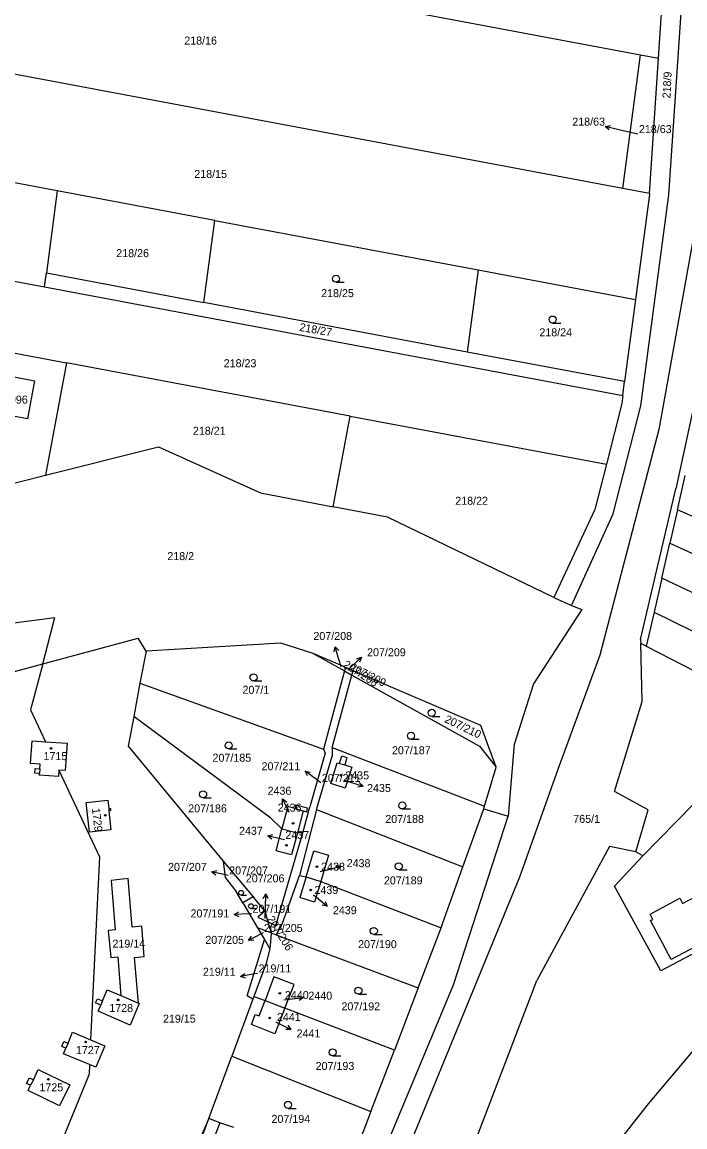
# Model space of a CAD drawing. Extents: x -735249 to -729401, y -1124843 to -1121828.
# Drawn here: x -733671.5 to -733530.7, y -1123483.1 to -1123248.5 of the extents above; entities that cross this region are included whole.
import ezdxf

# ---------------------------------------------------------------- set-up
doc = ezdxf.new("R2010")
doc.units = 0
for name, color, linetype in [('Vrstva 1', 7, 'Continuous'), ('Vrstva 10', 7, 'Continuous'), ('Vrstva 16', 7, 'Continuous'), ('Vrstva 18', 7, 'Continuous'), ('Vrstva 19', 7, 'Continuous'), ('Vrstva 25', 7, 'Continuous'), ('Vrstva 4', 7, 'Continuous')]:
    doc.layers.add(name, color=color, linetype=linetype)

msp = doc.modelspace()

# ---------------------------------------------------------------- linework, layer by layer
at = {"layer": 'Vrstva 1'}
for points in [[(-733736.92, -1123218.48), (-733540.13, -1123255.42)], [(-733536.3, -1123256.14), (-733535.11, -1123238.11)], [(-733534.07, -1123285.18), (-733530.92, -1123238.05)], [(-733543.83, -1123283.81), (-733727.57, -1123249.33)], [(-733543.83, -1123283.81), (-733540.13, -1123255.42)], [(-733540.13, -1123255.42), (-733536.3, -1123256.14)], [(-733538.21, -1123284.87), (-733536.3, -1123256.14)], [(-733664.04, -1123284.33), (-733718.36, -1123274.13)], [(-733664.04, -1123284.33), (-733666.35, -1123301.75)], [(-733630.59, -1123290.61), (-733664.04, -1123284.33)], [(-733538.21, -1123284.87), (-733543.83, -1123283.81)], [(-733538.22, -1123285.05), (-733541.18, -1123307.39)], [(-733540.03, -1123329.93), (-733534.07, -1123285.18)], [(-733538.21, -1123284.87), (-733538.22, -1123285.05)], [(-733632.9, -1123308.03), (-733630.59, -1123290.61)], [(-733630.59, -1123290.61), (-733574.63, -1123301.11)], [(-733520.99, -1123294.03), (-733532.59, -1123347.6)], [(-733710.01, -1123296.6), (-733666.75, -1123304.72)], [(-733666.75, -1123304.72), (-733666.35, -1123301.75)], [(-733666.35, -1123301.75), (-733632.9, -1123308.03)], [(-733574.63, -1123301.11), (-733576.94, -1123318.53)], [(-733574.63, -1123301.11), (-733541.18, -1123307.39)], [(-733666.75, -1123304.72), (-733543.89, -1123327.78)], [(-733576.94, -1123318.53), (-733632.9, -1123308.03)], [(-733541.18, -1123307.39), (-733543.5, -1123324.81)], [(-733702.78, -1123313.18), (-733662.06, -1123320.82)], [(-733543.5, -1123324.81), (-733576.94, -1123318.53)], [(-733662.06, -1123320.82), (-733666.55, -1123344.7)], [(-733601.77, -1123332.14), (-733662.06, -1123320.82)], [(-733674.99, -1123323.44), (-733668.9, -1123324.66), (-733670.38, -1123332.72), (-733676.51, -1123331.56), (-733674.99, -1123323.44)], [(-733543.89, -1123327.78), (-733543.5, -1123324.81)], [(-733544.11, -1123329.44), (-733547.36, -1123342.35)], [(-733545.89, -1123352.88), (-733540.03, -1123329.93)], [(-733543.89, -1123327.78), (-733544.11, -1123329.44)], [(-733605.39, -1123351.42), (-733601.77, -1123332.14)], [(-733601.77, -1123332.14), (-733547.36, -1123342.35)], [(-733666.55, -1123344.7), (-733642.54, -1123338.69)], [(-733642.54, -1123338.69), (-733620.86, -1123348.46)], [(-733547.36, -1123342.35), (-733549.78, -1123351.98)], [(-733687, -1123349.82), (-733666.55, -1123344.7)], [(-733532.26, -1123352.08), (-733530.59, -1123344.79)], [(-733620.86, -1123348.46), (-733605.39, -1123351.42)], [(-733540.08, -1123379.6), (-733532.59, -1123347.6)], [(-733593.86, -1123353.63), (-733605.39, -1123351.42)], [(-733549.78, -1123351.98), (-733558.54, -1123370.66)], [(-733554.78, -1123372.38), (-733545.89, -1123352.88)], [(-733532.26, -1123352.08), (-733533.89, -1123359.16)], [(-733483.93, -1123373.04), (-733532.26, -1123352.08)], [(-733558.54, -1123370.66), (-733593.86, -1123353.63)], [(-733535.59, -1123366.57), (-733533.89, -1123359.16)], [(-733533.89, -1123359.16), (-733485.79, -1123381.01)], [(-733535.59, -1123366.57), (-733537.24, -1123373.77)], [(-733487.7, -1123389.15), (-733535.59, -1123366.57)], [(-733558.54, -1123370.66), (-733554.78, -1123372.38)], [(-733552.6, -1123373.18), (-733562.87, -1123389.01)], [(-733554.78, -1123372.38), (-733552.6, -1123373.18)], [(-733537.24, -1123373.77), (-733538.91, -1123381.02)], [(-733537.24, -1123373.77), (-733489.57, -1123397.16)], [(-733673.24, -1123376.01), (-733664.56, -1123374.88)], [(-733667.14, -1123384.77), (-733664.56, -1123374.88)], [(-733667.14, -1123384.77), (-733646.84, -1123379.28)], [(-733645.17, -1123382.03), (-733646.84, -1123379.28)], [(-733616.54, -1123380.36), (-733645.17, -1123382.03)], [(-733609.7, -1123382.54), (-733616.54, -1123380.36)], [(-733540.08, -1123379.6), (-733540.06, -1123380.46)], [(-733538.91, -1123381.02), (-733540.06, -1123380.46)], [(-733539.76, -1123392.73), (-733540.06, -1123380.46)], [(-733538.91, -1123381.02), (-733491.48, -1123405.34)], [(-733645.17, -1123382.03), (-733646.47, -1123388.87)], [(-733609.7, -1123382.54), (-733603.04, -1123386.25)], [(-733602.84, -1123385.49), (-733609.7, -1123382.54)], [(-733680.02, -1123388.25), (-733667.14, -1123384.77)], [(-733667.14, -1123384.77), (-733669.7, -1123394.55)], [(-733603.04, -1123386.25), (-733607.45, -1123402.89)], [(-733602.84, -1123385.49), (-733603.04, -1123386.25)], [(-733603.04, -1123386.25), (-733601.43, -1123387.15)], [(-733601.17, -1123386.21), (-733602.84, -1123385.49)], [(-733601.43, -1123387.15), (-733601.17, -1123386.21)], [(-733574.03, -1123397.88), (-733601.17, -1123386.21)], [(-733605.65, -1123402.51), (-733601.43, -1123387.15)], [(-733601.43, -1123387.15), (-733574.32, -1123402.24)], [(-733646.47, -1123388.87), (-733647.81, -1123395.96)], [(-733646.47, -1123388.87), (-733607.45, -1123402.89)], [(-733562.87, -1123389.01), (-733566.96, -1123401.86)], [(-733545.62, -1123411.89), (-733539.76, -1123392.73)], [(-733669.7, -1123394.55), (-733666.54, -1123401.28)], [(-733647.81, -1123395.96), (-733649.01, -1123402.27)], [(-733618.66, -1123417.51), (-733647.81, -1123395.96)], [(-733570.75, -1123406.68), (-733574.03, -1123397.88)], [(-733669.72, -1123405.91), (-733669.38, -1123401.08)], [(-733669.38, -1123401.08), (-733666.54, -1123401.28)], [(-733666.54, -1123401.28), (-733661.93, -1123401.61)], [(-733661.93, -1123401.61), (-733662.35, -1123407.43)], [(-733649.01, -1123402.27), (-733628.78, -1123426.64)], [(-733605.65, -1123402.51), (-733605.6, -1123404.35)], [(-733605.65, -1123402.51), (-733573.24, -1123414.96)], [(-733574.32, -1123402.24), (-733570.75, -1123406.68)], [(-733566.96, -1123401.86), (-733568.25, -1123417.12)], [(-733607.12, -1123403.71), (-733610.4, -1123415.14)], [(-733608.94, -1123415.67), (-733605.6, -1123404.35)], [(-733607.45, -1123402.89), (-733607.12, -1123403.71)], [(-733604.08, -1123405.89), (-733603.6, -1123404.31)], [(-733603.6, -1123404.31), (-733602.48, -1123404.65)], [(-733602.48, -1123404.65), (-733602.96, -1123406.23)], [(-733667.69, -1123406.06), (-733669.72, -1123405.91)], [(-733668.81, -1123407.96), (-733668.75, -1123406.97)], [(-733668.75, -1123406.97), (-733667.76, -1123407.04)], [(-733667.76, -1123407.04), (-733667.69, -1123406.06)], [(-733663.68, -1123407.33), (-733663.78, -1123408.71)], [(-733662.35, -1123407.43), (-733663.68, -1123407.33)], [(-733663.68, -1123407.33), (-733655.07, -1123425.73)], [(-733605.9, -1123410.18), (-733604.55, -1123405.77)], [(-733604.55, -1123405.77), (-733604.08, -1123405.89)], [(-733602.96, -1123406.23), (-733601.47, -1123406.68)], [(-733601.47, -1123406.68), (-733602.84, -1123411.13)], [(-733573.24, -1123414.96), (-733570.75, -1123406.68)], [(-733667.83, -1123408.03), (-733668.81, -1123407.96)], [(-733667.86, -1123408.42), (-733667.83, -1123408.03)], [(-733663.78, -1123408.71), (-733667.86, -1123408.42)], [(-733602.84, -1123411.13), (-733605.9, -1123410.18)], [(-733538.5, -1123415.76), (-733545.62, -1123411.89)], [(-733657.87, -1123414.17), (-733653.29, -1123413.69)], [(-733657.21, -1123420.49), (-733657.87, -1123414.17)], [(-733653.29, -1123413.69), (-733653.1, -1123415.49)], [(-733653.1, -1123415.49), (-733652.76, -1123415.46)], [(-733652.72, -1123415.92), (-733653.06, -1123415.95)], [(-733653.06, -1123415.95), (-733652.63, -1123420.01)], [(-733652.76, -1123415.46), (-733652.72, -1123415.92)], [(-733615.06, -1123415.08), (-733616.3, -1123419.76)], [(-733613.57, -1123415.48), (-733615.06, -1123415.08)], [(-733613.37, -1123414.73), (-733613.57, -1123415.48)], [(-733610.84, -1123415.41), (-733613.37, -1123414.73)], [(-733611.77, -1123415.96), (-733613.02, -1123420.64)], [(-733608.94, -1123415.67), (-733612.6, -1123429.68)], [(-733611.87, -1123420.65), (-733610.4, -1123415.14)], [(-733611.77, -1123415.96), (-733611.04, -1123416.16)], [(-733611.04, -1123416.16), (-733610.84, -1123415.41)], [(-733608.94, -1123415.67), (-733577.83, -1123427.85)], [(-733577.83, -1123427.85), (-733573.41, -1123415.52)], [(-733573.41, -1123415.52), (-733573.37, -1123415.4)], [(-733573.41, -1123415.52), (-733568.25, -1123417.12)], [(-733573.37, -1123415.4), (-733573.24, -1123414.96)], [(-733541.12, -1123424.68), (-733538.5, -1123415.76)], [(-733539.61, -1123425.5), (-733528.95, -1123414.64)], [(-733616.3, -1123419.76), (-733618.66, -1123417.51)], [(-733579.85, -1123452.94), (-733568.25, -1123417.12)], [(-733652.63, -1123420.01), (-733657.21, -1123420.49)], [(-733617.62, -1123440.35), (-733611.87, -1123420.65)], [(-733617.55, -1123424.43), (-733616.3, -1123419.76)], [(-733616.3, -1123419.76), (-733613.02, -1123420.64)], [(-733613.02, -1123420.64), (-733614.27, -1123425.32)], [(-733611.87, -1123420.65), (-733613.02, -1123420.64)], [(-733546.73, -1123423.51), (-733562.11, -1123452.02)], [(-733541.12, -1123424.68), (-733546.73, -1123423.51)], [(-733655.07, -1123425.73), (-733656.95, -1123464.59)], [(-733614.27, -1123425.32), (-733617.55, -1123424.43)], [(-733611.18, -1123430), (-733609.52, -1123424.46)], [(-733609.52, -1123424.46), (-733606.4, -1123425.4)], [(-733606.4, -1123425.4), (-733608.06, -1123430.94)], [(-733545.65, -1123431.95), (-733539.61, -1123425.5)], [(-733539.61, -1123425.5), (-733541.12, -1123424.68)], [(-733628.78, -1123426.64), (-733628.38, -1123430.15)], [(-733628.78, -1123426.64), (-733622.43, -1123434.26)], [(-733582.09, -1123439.73), (-733577.83, -1123427.85)], [(-733648.98, -1123430.32), (-733652.6, -1123430.73)], [(-733652.6, -1123430.73), (-733651.77, -1123441.23)], [(-733648.13, -1123440.64), (-733648.98, -1123430.32)], [(-733628.38, -1123430.15), (-733626.02, -1123433.12)], [(-733616.22, -1123440.06), (-733612.6, -1123429.68)], [(-733612.6, -1123429.68), (-733611.18, -1123430)], [(-733611.18, -1123430), (-733612.49, -1123434.39)], [(-733611.18, -1123430), (-733608.06, -1123430.94)], [(-733608.06, -1123430.94), (-733609.39, -1123435.34)], [(-733608.06, -1123430.94), (-733582.49, -1123440.79)], [(-733624.6, -1123435.53), (-733626.02, -1123433.12)], [(-733535.76, -1123449.95), (-733545.65, -1123431.95)], [(-733622.43, -1123434.26), (-733624.6, -1123435.53)], [(-733624.6, -1123435.53), (-733621.5, -1123440.79)], [(-733622.43, -1123434.26), (-733622.1, -1123434.65)], [(-733622.1, -1123434.65), (-733619.95, -1123437.26)], [(-733609.39, -1123435.34), (-733612.49, -1123434.39)], [(-733538.08, -1123437.88), (-733531.78, -1123434.55)], [(-733506.88, -1123433.46), (-733533.58, -1123447.57)], [(-733531.78, -1123434.55), (-733531.18, -1123435.68)], [(-733531.18, -1123435.68), (-733526.89, -1123433.4)], [(-733619.95, -1123437.26), (-733621.44, -1123438.55)], [(-733619.95, -1123437.26), (-733619.29, -1123439.57)], [(-733537.49, -1123439.01), (-733538.08, -1123437.88)], [(-733621.44, -1123438.55), (-733619.29, -1123439.57)], [(-733619.29, -1123439.57), (-733617.62, -1123440.35)], [(-733619.29, -1123439.57), (-733618.62, -1123441.86)], [(-733617.5, -1123442.28), (-733616.22, -1123440.06)], [(-733582.49, -1123440.79), (-733582.09, -1123439.73)], [(-733537.96, -1123439.26), (-733537.49, -1123439.01)], [(-733533.58, -1123447.57), (-733537.96, -1123439.26)], [(-733651.77, -1123441.23), (-733653.2, -1123441.38)], [(-733653.2, -1123441.38), (-733652.69, -1123447.11)], [(-733646.08, -1123440.47), (-733648.13, -1123440.64)], [(-733645.58, -1123446.93), (-733646.08, -1123440.47)], [(-733621.5, -1123440.79), (-733620.03, -1123443.28)], [(-733618.62, -1123441.86), (-733621.5, -1123440.79)], [(-733618.56, -1123442.08), (-733618.85, -1123445.28)], [(-733618.62, -1123441.86), (-733618.56, -1123442.08)], [(-733618.62, -1123441.86), (-733617.5, -1123442.28)], [(-733617.5, -1123442.28), (-733587.36, -1123453.53)], [(-733587.36, -1123453.53), (-733582.49, -1123440.79)], [(-733518.47, -1123440.79), (-733535.76, -1123449.95)], [(-733623.68, -1123455.23), (-733620.03, -1123443.28)], [(-733620.03, -1123443.28), (-733618.85, -1123445.28)], [(-733652.69, -1123447.11), (-733651.2, -1123446.99)], [(-733651.2, -1123446.99), (-733650.53, -1123455.22)], [(-733647.6, -1123447.09), (-733645.58, -1123446.93)], [(-733646.81, -1123456.81), (-733647.6, -1123447.09)], [(-733618.85, -1123445.28), (-733619.65, -1123448.32)], [(-733538.42, -1123478.16), (-733511.36, -1123446.1)], [(-733619.65, -1123448.32), (-733622.27, -1123455.38)], [(-733617.99, -1123451.22), (-733619.89, -1123456.26)], [(-733613.72, -1123452.83), (-733617.99, -1123451.22)], [(-733583.6, -1123508.04), (-733562.11, -1123452.02)], [(-733654.43, -1123456.33), (-733653.42, -1123453.98)], [(-733653.42, -1123453.98), (-733650.53, -1123455.22)], [(-733615.68, -1123457.88), (-733613.72, -1123452.83)], [(-733598.75, -1123498.25), (-733579.85, -1123452.94)], [(-733587.36, -1123453.53), (-733592.41, -1123466.78)], [(-733655.89, -1123456.77), (-733655.5, -1123455.86)], [(-733655.5, -1123455.86), (-733654.43, -1123456.33)], [(-733650.53, -1123455.22), (-733646.81, -1123456.81)], [(-733622.49, -1123455.97), (-733626.97, -1123468.09)], [(-733622.49, -1123455.97), (-733623.68, -1123455.23)], [(-733622.27, -1123455.38), (-733622.49, -1123455.97)], [(-733622.27, -1123455.38), (-733619.89, -1123456.26)], [(-733621.12, -1123459.53), (-733619.89, -1123456.26)], [(-733619.89, -1123456.26), (-733615.68, -1123457.88)], [(-733654.81, -1123457.23), (-733655.89, -1123456.77)], [(-733655.37, -1123458.53), (-733654.81, -1123457.23)], [(-733648.58, -1123461.45), (-733655.37, -1123458.53)], [(-733646.63, -1123456.89), (-733648.58, -1123461.45)], [(-733646.81, -1123456.81), (-733646.63, -1123456.89)], [(-733615.68, -1123457.88), (-733617.79, -1123463.32)], [(-733592.41, -1123466.78), (-733615.68, -1123457.88)], [(-733622.74, -1123461.33), (-733621.97, -1123459.21)], [(-733617.79, -1123463.32), (-733622.74, -1123461.33)], [(-733621.97, -1123459.21), (-733621.12, -1123459.53)], [(-733661.76, -1123465.33), (-733660.78, -1123462.98)], [(-733660.78, -1123462.98), (-733656.95, -1123464.59)], [(-733663.07, -1123465.99), (-733662.64, -1123464.97)], [(-733662.2, -1123466.35), (-733663.07, -1123465.99)], [(-733662.64, -1123464.97), (-733661.76, -1123465.33)], [(-733656.95, -1123464.59), (-733653.95, -1123465.85)], [(-733653.95, -1123465.85), (-733655.88, -1123470.43)], [(-733662.7, -1123467.55), (-733662.2, -1123466.35)], [(-733657.2, -1123469.87), (-733662.7, -1123467.55)], [(-733631.86, -1123481.32), (-733626.97, -1123468.09)], [(-733626.97, -1123468.09), (-733597.4, -1123479.83)], [(-733597.4, -1123479.83), (-733592.41, -1123466.78)], [(-733657.2, -1123469.87), (-733657.3, -1123471.92)], [(-733655.88, -1123470.43), (-733657.2, -1123469.87)], [(-733670.55, -1123473.85), (-733669.98, -1123472.66)], [(-733669.98, -1123472.66), (-733669.12, -1123473.08)], [(-733669.12, -1123473.08), (-733668.08, -1123470.93)], [(-733668.08, -1123470.93), (-733661.39, -1123474.17)], [(-733657.3, -1123471.92), (-733667.02, -1123495.8)], [(-733669.7, -1123474.26), (-733670.55, -1123473.85)], [(-733670.24, -1123475.39), (-733669.7, -1123474.26)], [(-733663.55, -1123478.63), (-733670.24, -1123475.39)], [(-733661.39, -1123474.17), (-733663.55, -1123478.63)], [(-733597.4, -1123479.83), (-733601.93, -1123491.71)], [(-733582.62, -1123534.37), (-733538.42, -1123478.16)], [(-733631.86, -1123481.32), (-733636.56, -1123492.2)], [(-733635.91, -1123492.28), (-733631.86, -1123481.32)], [(-733629.53, -1123482.24), (-733631.86, -1123481.32)], [(-733629.53, -1123482.24), (-733631.58, -1123487.53)], [(-733626.53, -1123483.25), (-733629.53, -1123482.24)]]:
    msp.add_lwpolyline(points, dxfattribs=at)
at = {"layer": 'Vrstva 10'}
msp.add_lwpolyline([(-733554.55, -1122875.4), (-733527.93, -1123135.14), (-733525.72, -1123160.85), (-733524.03, -1123186.32), (-733523.36, -1123211.8), (-733523.33, -1123236.18), (-733524.81, -1123261.05), (-733527.46, -1123286.21), (-733536.18, -1123335), (-733548.72, -1123382.9), (-733557.6, -1123406.95), (-733565.8, -1123430.03), (-733599.27, -1123511.46), (-733632.77, -1123591.76), (-733662.7, -1123662.58), (-733683.9, -1123713.51), (-733745.65, -1123859.1)], dxfattribs=at)
at = {"layer": 'Vrstva 16'}
for points in [[(-733540.65, -1123272.24), (-733544.68, -1123271.33)], [(-733603.74, -1123385.38), (-733604.14, -1123384.01)], [(-733602.33, -1123386.09), (-733601.59, -1123385.4)], [(-733608.02, -1123410.03), (-733608.97, -1123409.33)], [(-733603.04, -1123409.49), (-733601.92, -1123409.84)], [(-733614.75, -1123416.33), (-733614.85, -1123416.12)], [(-733615.78, -1123422.15), (-733616.41, -1123421.99)], [(-733608.17, -1123428.88), (-733606.65, -1123428.49)], [(-733627.71, -1123429.68), (-733628.32, -1123429.55)], [(-733609.59, -1123433.83), (-733608.99, -1123434.32)], [(-733622.76, -1123437.82), (-733623.43, -1123437.85)], [(-733619.84, -1123438.84), (-733619.8, -1123436.61)], [(-733620.32, -1123441.89), (-733620.75, -1123442.11)], [(-733621.47, -1123450.48), (-733622.16, -1123450.61)], [(-733615.87, -1123456.14), (-733614.69, -1123455.99)], [(-733617.57, -1123460.8), (-733617.07, -1123461.05)]]:
    msp.add_lwpolyline(points, dxfattribs=at)
at = {"layer": 'Vrstva 25'}
for points in [[(-733546.741, -1123271.374), (-733547.605, -1123270.666), (-733546.519, -1123270.4)], [(-733544.68, -1123271.33), (-733547.605, -1123270.666)], [(-733604.81, -1123303.72), (-733603.06, -1123303.72)], [(-733558.79, -1123312.39), (-733557.04, -1123312.39)], [(-733605.178, -1123382.229), (-733604.976, -1123381.13), (-733604.217, -1123381.95)], [(-733604.14, -1123384.01), (-733604.976, -1123381.13)], [(-733601.59, -1123385.4), (-733599.404, -1123383.347)], [(-733600.475, -1123383.667), (-733599.404, -1123383.347), (-733599.79, -1123384.396)], [(-733622.33, -1123388.39), (-733620.58, -1123388.39)], [(-733584.47, -1123395.91), (-733582.72, -1123395.91)], [(-733588.87, -1123400.78), (-733587.12, -1123400.78)], [(-733627.63, -1123402.82), (-733625.88, -1123402.82)], [(-733608.97, -1123409.33), (-733611.381, -1123407.546)], [(-733610.875, -1123408.543), (-733611.381, -1123407.546), (-733610.28, -1123407.739)], [(-733601.92, -1123409.84), (-733599.058, -1123410.737)], [(-733599.862, -1123409.96), (-733599.058, -1123410.737), (-733600.162, -1123410.915)], [(-733633.06, -1123413.21), (-733631.31, -1123413.21)], [(-733616.17, -1123414.537), (-733616.155, -1123413.42), (-733615.27, -1123414.102)], [(-733614.85, -1123416.12), (-733616.155, -1123413.42)], [(-733590.73, -1123415.57), (-733588.98, -1123415.57)], [(-733618.471, -1123421.985), (-733619.318, -1123421.255), (-733618.226, -1123421.015)], [(-733616.41, -1123421.99), (-733619.318, -1123421.255)], [(-733606.65, -1123428.49), (-733603.746, -1123427.739)], [(-733604.839, -1123427.506), (-733603.746, -1123427.739), (-733604.589, -1123428.474)], [(-733591.47, -1123428.51), (-733589.72, -1123428.51)], [(-733630.38, -1123429.616), (-733631.252, -1123428.917), (-733630.169, -1123428.639)], [(-733628.32, -1123429.55), (-733631.252, -1123428.917)], [(-733624.98, -1123433.87), (-733623.807, -1123433.87)], [(-733620.265, -1123434.602), (-733619.748, -1123433.611), (-733619.266, -1123434.62)], [(-733619.8, -1123436.61), (-733619.748, -1123433.611)], [(-733608.99, -1123434.32), (-733606.672, -1123436.224)], [(-733607.128, -1123435.203), (-733606.672, -1123436.224), (-733607.762, -1123435.975)], [(-733625.403, -1123438.447), (-733626.426, -1123437.996), (-733625.452, -1123437.449)], [(-733623.43, -1123437.85), (-733626.426, -1123437.996)], [(-733622.89, -1123436.71), (-733621.717, -1123436.71)], [(-733620.75, -1123442.11), (-733623.418, -1123443.481)], [(-733622.3, -1123443.468), (-733623.418, -1123443.481), (-733622.757, -1123442.579)], [(-733596.78, -1123442.23), (-733595.03, -1123442.23)], [(-733624.027, -1123451.482), (-733625.104, -1123451.182), (-733624.218, -1123450.501)], [(-733622.16, -1123450.61), (-733625.104, -1123451.182)], [(-733614.69, -1123455.99), (-733611.714, -1123455.615)], [(-733612.769, -1123455.244), (-733611.714, -1123455.615), (-733612.644, -1123456.235)], [(-733600.05, -1123454.91), (-733598.3, -1123454.91)], [(-733617.07, -1123461.05), (-733614.388, -1123462.393)], [(-733615.058, -1123461.498), (-733614.388, -1123462.393), (-733615.506, -1123462.392)], [(-733605.54, -1123468.01), (-733603.79, -1123468.01)], [(-733615.01, -1123479.16), (-733613.26, -1123479.16)]]:
    msp.add_lwpolyline(points, dxfattribs=at)
for centre, radius in [((-733604.81, -1123302.97), 0.75), ((-733558.79, -1123311.64), 0.75), ((-733622.33, -1123387.64), 0.75), ((-733584.47, -1123395.16), 0.75), ((-733588.87, -1123400.03), 0.75), ((-733665.39, -1123402.72), 0.175), ((-733627.63, -1123402.07), 0.75), ((-733603.75, -1123408.43), 0.175), ((-733633.06, -1123412.46), 0.75), ((-733590.73, -1123414.82), 0.75), ((-733653.83, -1123416.94), 0.175), ((-733613.92, -1123418.61), 0.175), ((-733615.34, -1123423.3), 0.175), ((-733608.88, -1123427.81), 0.175), ((-733591.47, -1123427.76), 0.75), ((-733624.98, -1123433.367), 0.503), ((-733610.21, -1123432.77), 0.175), ((-733622.89, -1123436.208), 0.503), ((-733596.78, -1123441.48), 0.75), ((-733600.05, -1123454.16), 0.75), ((-733651.1, -1123456.11), 0.175), ((-733616.75, -1123454.73), 0.175), ((-733618.9, -1123459.96), 0.175), ((-733658.02, -1123465.05), 0.175), ((-733605.54, -1123467.26), 0.75), ((-733665.94, -1123472.97), 0.175), ((-733615.01, -1123478.41), 0.75)]:
    msp.add_circle(centre, radius, dxfattribs=at)
at = {"layer": 'Vrstva 4'}
for points in [[(-733667.76, -1123407.04), (-733667.83, -1123408.03)], [(-733604.08, -1123405.89), (-733602.96, -1123406.23)], [(-733653.1, -1123415.49), (-733653.06, -1123415.95)], [(-733613.57, -1123415.48), (-733611.77, -1123415.96)], [(-733654.43, -1123456.33), (-733654.81, -1123457.23)], [(-733661.76, -1123465.33), (-733662.2, -1123466.35)], [(-733669.12, -1123473.08), (-733669.7, -1123474.26)]]:
    msp.add_lwpolyline(points, dxfattribs=at)

# ---------------------------------------------------------------- texts
at = {"layer": 'Vrstva 16'}
for s, p in [('218/63', (-733554.607, -1123270.47)), ('207/208', (-733609.62, -1123379.69)), ('207/209', (-733598.21, -1123383.14)), ('207/211', (-733620.637, -1123407.35)), ('2436', (-733619.353, -1123412.55)), ('2435', (-733598.22, -1123411.98)), ('765/1', (-733554.398, -1123418.53)), ('2437', (-733625.426, -1123421.06)), ('2438', (-733602.55, -1123427.93)), ('207/207', (-733640.507, -1123428.72)), ('207/206', (-733623.99, -1123431.16)), ('207/191', (-733635.727, -1123438.6)), ('2439', (-733605.47, -1123437.92)), ('207/205', (-733632.587, -1123444.22)), ('219/11', (-733633.097, -1123450.99)), ('2440', (-733610.68, -1123456.07)), ('2441', (-733613.19, -1123464.09))]:
    msp.add_text(s, height=1.7, dxfattribs=at).set_placement(p)
at = {"layer": 'Vrstva 18'}
for s, p in [('218/16', (-733637.06, -1123253.24)), ('218/63', (-733540.45, -1123272.04)), ('218/15', (-733634.93, -1123281.57)), ('218/26', (-733651.51, -1123298.39)), ('218/25', (-733607.97, -1123306.88)), ('218/24', (-733561.6, -1123315.2)), ('218/23', (-733628.68, -1123321.76)), ('218/21', (-733635.22, -1123336.1)), ('218/22', (-733579.47, -1123350.97)), ('218/2', (-733640.66, -1123362.73)), ('207/1', (-733624.69, -1123391.11)), ('207/187', (-733592.92, -1123403.95)), ('207/185', (-733631.06, -1123405.54)), ('207/211', (-733607.82, -1123409.83)), ('207/186', (-733636.22, -1123416.29)), ('207/188', (-733594.34, -1123418.55)), ('207/207', (-733627.51, -1123429.48)), ('207/189', (-733594.63, -1123431.59)), ('207/191', (-733622.56, -1123437.62)), ('207/205', (-733620.12, -1123441.69)), ('219/14', (-733652.32, -1123445.02)), ('207/190', (-733600.12, -1123445.13)), ('219/11', (-733621.27, -1123450.28)), ('207/192', (-733603.66, -1123458.34)), ('219/15', (-733641.58, -1123460.96)), ('207/193', (-733609.14, -1123471)), ('207/194', (-733618.52, -1123482.24))]:
    msp.add_text(s, height=1.7, dxfattribs=at).set_placement(p)
for s, rotation, p in [('218/9', 87.10069, (-733533.759, -1123264.711)), ('218/27', 350.20279, (-733612.689, -1123314.027)), ('207/208', 327.60261, (-733603.464, -1123385.319)), ('207/209', 333.40265, (-733602.062, -1123386.001)), ('207/210', 334.10266, (-733581.883, -1123397.058)), ('207/206', 301.7024, (-733619.565, -1123438.905))]:
    msp.add_text(s, height=1.7, rotation=rotation, dxfattribs=at).set_placement(p)
at = {"layer": 'Vrstva 19'}
for s, p in [('3096', (-733675.373, -1123329.49)), ('1715', (-733666.97, -1123405.2)), ('2435', (-733602.84, -1123409.29)), ('2436', (-733617.203, -1123416.13)), ('2437', (-733615.58, -1123421.95)), ('2438', (-733607.97, -1123428.68)), ('2439', (-733609.39, -1123433.63)), ('2440', (-733615.67, -1123455.94)), ('1728', (-733652.99, -1123458.69)), ('2441', (-733617.37, -1123460.6)), ('1727', (-733660.08, -1123467.63)), ('1725', (-733667.84, -1123475.54))]:
    msp.add_text(s, height=1.7, dxfattribs=at).set_placement(p)
msp.add_text('1729', height=1.7, rotation=276.6022, dxfattribs=at).set_placement((-733656.679, -1123415.475))

doc.saveas('drawing.dxf')
